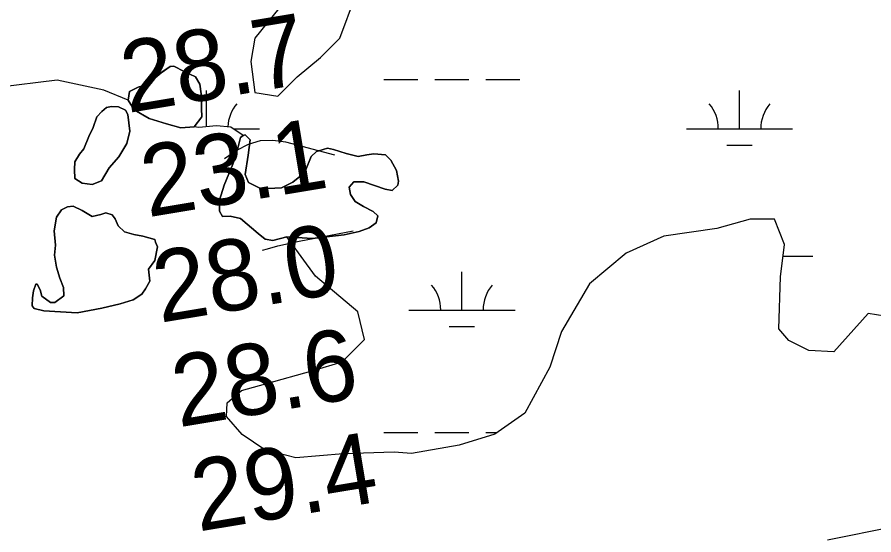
# Model space of a CAD drawing. Extents: x 3297772 to 3335630, y 634068 to 659439.
# Drawn here: x 3328306 to 3329113, y 647977 to 648465 of the extents above; entities that cross this region are included whole.
import ezdxf

# ---------------------------------------------------------------- set-up
doc = ezdxf.new("R2010")
doc.units = 0
for name, color, linetype in [('V-RIVR-EDGE', 7, 'Continuous'), ('V-RIVR-RANG', 7, 'Continuous'), ('V-SITE-VEGE', 7, 'Continuous'), ('V-TOPO-MAJR', 7, 'Continuous'), ('V-TOPO-SHOR', 7, 'Continuous'), ('V-WETL-SWMP', 7, 'Continuous')]:
    doc.layers.add(name, color=color, linetype=linetype)

msp = doc.modelspace()

# ---------------------------------------------------------------- linework, layer by layer
at = {"layer": 'V-RIVR-EDGE'}
msp.add_spline([(3333439.4, 648130.07), (3333432.26, 648128.6), (3333393.46, 648121.33), (3333365.91, 648117.13), (3333332.17, 648114.89), (3333298.43, 648114.2), (3333260.81, 648112.74), (3333230.17, 648112.04), (3333195.26, 648109.02), (3333136.3, 648102.97), (3333088.59, 648097.65), (3333047.08, 648092.71), (3333001.69, 648085.07), (3332967.93, 648078.95), (3332933.41, 648077.1), (3332910.92, 648075.99), (3332895.01, 648074.48), (3332874.46, 648073.36), (3332860.88, 648070.3), (3332849.23, 648064.89), (3332842.24, 648062.97), (3332806.95, 648061.9), (3332785.23, 648058.07), (3332742.94, 648051.2), (3332702.21, 648046.26), (3332606, 648034.47), (3332570.7, 648028.35), (3332514.83, 648018.8), (3332458.57, 648008.85), (3332396.12, 648000.48), (3332317.75, 647987.87), (3332285.55, 647982.52), (3332246.36, 647976.42), (3332207.96, 647971.86), (3332152.88, 647965.79), (3332088.49, 647961.29), (3332048.92, 647954.8), (3332019.05, 647950.22), (3331983.35, 647943.33), (3331945.33, 647935.66), (3331898, 647927.64), (3331843.29, 647918.08), (3331788.98, 647907.74), (3331738.16, 647900.5), (3331714.11, 647898.62), (3331693.93, 647894.02), (3331644.66, 647886.77), (3331609.35, 647880.26), (3331580.26, 647876.07), (3331563.2, 647876.11), (3331548.07, 647876.54), (3331538.38, 647876.17), (3331524.8, 647873.88), (3331503.46, 647868.5), (3331463.88, 647860.46), (3331402.97, 647851.3), (3331393.27, 647846.67), (3331382.01, 647841.27), (3331348.64, 647836.31), (3331302.48, 647830.22), (3331254.77, 647825.68), (3331162.07, 647821.65), (3331119.02, 647820.59), (3331084.5, 647817.19), (3331048.03, 647811.07), (3330992.95, 647804.62), (3330947.56, 647800.07), (3330916.92, 647796.66), (3330882.01, 647795.19), (3330846.71, 647791.4), (3330781.94, 647785.75), (3330745.08, 647780.02), (3330721.81, 647780.08), (3330687.31, 647783.65), (3330659, 647784.89), (3330629.53, 647784.57), (3330565.14, 647780.08), (3330512.78, 647775.17), (3330464.29, 647771.41), (3330411.15, 647764.95), (3330328.91, 647756.62), (3330280.81, 647752.47), (3330223.01, 647743.69), (3330159.77, 647733.77), (3330098.87, 647726.16), (3330018.57, 647717.05), (3329963.87, 647709.43), (3329917.71, 647702.95), (3329903.36, 647702.21), (3329890.56, 647702.25), (3329873.51, 647706.94), (3329862.26, 647707.75), (3329851.79, 647705.83), (3329827.73, 647698.91), (3329814.54, 647697.39), (3329809.49, 647696.63), (3329807.95, 647698.57), (3329806.79, 647701.68), (3329801.75, 647702.08), (3329782.75, 647701.35), (3329745.51, 647698.73), (3329718.75, 647695.69), (3329678.02, 647692.69), (3329648.15, 647688.88), (3329601.98, 647682.02), (3329556.21, 647675.93), (3329520.91, 647674.46), (3329508.12, 647675.27), (3329497.27, 647678.4), (3329465.46, 647674.6), (3329435.21, 647672.74), (3329406.12, 647671.26), (3329386.73, 647673.24), (3329372.01, 647678.71), (3329360.77, 647680.68), (3329347.58, 647681.48), (3329329.36, 647681.14), (3329318.87, 647676.51), (3329309.95, 647675.37), (3329285.52, 647674.66), (3329264.18, 647671.22), (3329230.05, 647668.98), (3329205.62, 647670.98), (3329192.82, 647669.46), (3329173.82, 647668.34), (3329159.86, 647669.54), (3329154.82, 647672.65), (3329142.02, 647669.97), (3329119.52, 647667.31), (3329104.39, 647666.19), (3329092.37, 647665.05), (3329070.26, 647665.11), (3329052.42, 647664.38), (3329042.73, 647664.79), (3329037.31, 647667.13), (3329035.38, 647670.62), (3329031.12, 647672.96), (3329023.36, 647673.37), (3329005.91, 647675.35), (3328975.68, 647679.3), (3328944.66, 647682.09), (3328895.41, 647682.6), (3328867.5, 647686.55), (3328838.8, 647688.56), (3328809.34, 647690.18), (3328773.66, 647691.82), (3328729.06, 647689.61), (3328666.24, 647693.64), (3328624.75, 647694.91), (3328580.16, 647695.79), (3328546.8, 647693.55), (3328506.84, 647687.05), (3328492.87, 647683.21), (3328482.77, 647675.09), (3328471.9, 647673.18), (3328434.28, 647669.78), (3328399.37, 647666.77), (3328372.6, 647660.63), (3328345.83, 647656.43), (3328313.24, 647653.41), (3328276.01, 647651.56), (3328220.15, 647646.27), (3328210.45, 647641.64), (3328198.03, 647638.18), (3328173.59, 647636.69), (3328112.7, 647631.8), (3328044.04, 647626.54), (3328041.33, 647628.48), (3328031.68, 647644.02), (3328021.23, 647654.52), (3328011.16, 647660.36), (3327997.99, 647665.82), (3327984.43, 647668.96), (3327951.08, 647672.14), (3327903.39, 647674.97), (3327857.25, 647678.58), (3327817.69, 647677.9), (3327782.79, 647676.43), (3327750.6, 647676.13), (3327707.94, 647675.46), (3327667.61, 647675.56), (3327640.47, 647680.28), (3327623.8, 647683.03), (3327599.38, 647684.26), (3327563.3, 647682.02), (3327529.17, 647680.16), (3327489.22, 647675.22), (3327442.66, 647667.58), (3327414.73, 647665.71), (3327389.53, 647666.16), (3327373.63, 647665.42), (3327367.43, 647667.38), (3327351.54, 647674.4), (3327334.11, 647680.26), (3327331.79, 647683.75), (3327330.25, 647688.8), (3327320.56, 647691.93), (3327317.47, 647695.81), (3327317.87, 647700.85), (3327315.16, 647702.8), (3327303.15, 647707.09), (3327298.5, 647707.49), (3327292.29, 647704.79), (3327281.81, 647701.72), (3327271.72, 647701.74), (3327235.27, 647702.22), (3327199.21, 647703.47), (3327168.96, 647704.32), (3327108.86, 647708.35), (3327072.81, 647712.7), (3327031.71, 647717.46), (3326986.73, 647719.9), (3326955.32, 647719.2), (3326928.95, 647718.1), (3326908, 647716.21), (3326887.82, 647708.12), (3326876.17, 647702.72), (3326868.8, 647701.96), (3326856.78, 647704.71), (3326842.05, 647704.74), (3326809.47, 647703.27), (3326777.27, 647698.31), (3326760.2, 647695.64), (3326748.94, 647691.4), (3326738.08, 647689.49), (3326737.31, 647691.04), (3326736.93, 647694.92), (3326734.61, 647696.86), (3326712.9, 647700.41), (3326678.39, 647702.05), (3326660.16, 647703.64), (3326628.38, 647711.48), (3326607.84, 647715.41), (3326582.63, 647714.3), (3326557.02, 647710.1), (3326535.69, 647708.99), (3326505.83, 647710.23), (3326475.98, 647711.85), (3326436.81, 647712.73), (3326394.54, 647711.67), (3326361.58, 647711.75), (3326334.82, 647714.14), (3326302.66, 647722.75), (3326245.3, 647737.63), (3326217.01, 647746.62), (3326194.53, 647752.11), (3326171.27, 647755.65), (3326147.62, 647755.32), (3326132.09, 647751.1), (3326110.74, 647743), (3326100.26, 647739.15), (3326091.73, 647738.79), (3326082.82, 647741.52), (3326084.38, 647746.17), (3326084.39, 647749.66), (3326081.3, 647753.16), (3326059.58, 647751.28), (3326025.83, 647748.26), (3325980.44, 647741), (3325936.6, 647735.29)], degree=3, dxfattribs=at)
at = {"layer": 'V-SITE-VEGE'}
msp.add_lwpolyline([(3328559.27, 648481.04), (3328530.13, 648444.6), (3328526.48, 648422.73), (3328530.13, 648393.58), (3328551.98, 648389.93), (3328570.19, 648408.15), (3328592.05, 648426.38), (3328610.26, 648444.6), (3328624.83, 648484.69)], dxfattribs=at)
for points in [[(3328428.72, 648400.97), (3328420.18, 648398.65), (3328412.02, 648394.39), (3328410.84, 648386.23), (3328416.66, 648377.3), (3328430.63, 648369.13), (3328446.93, 648364.06), (3328460.51, 648360.16), (3328472.94, 648361.31), (3328480.33, 648370.62), (3328479.95, 648378.39), (3328479.58, 648392.37), (3328478.42, 648401.3), (3328474.16, 648408.29), (3328463.68, 648413.35), (3328453.98, 648418.41), (3328450.48, 648418.03), (3328441.94, 648412.21)], [(3328369.24, 648340.47), (3328364.97, 648335.42), (3328360.69, 648328.05), (3328360.29, 648321.06), (3328360.67, 648312.52), (3328367.65, 648308.24), (3328376.97, 648306.68), (3328385.9, 648310.16), (3328392.91, 648322.58), (3328402.24, 648333.05), (3328409.63, 648345.47), (3328412.36, 648357.11), (3328410.44, 648372.65), (3328408.5, 648376.92), (3328401.91, 648380.03), (3328395.3, 648380.43), (3328390.64, 648379.27), (3328385.98, 648375.78), (3328381.31, 648370.74), (3328377.81, 648360.65), (3328373.92, 648352.11)], [(3328583.18, 648333.23), (3328577.73, 648320.03), (3328574.23, 648315.77), (3328566.07, 648309.17), (3328555.19, 648303.75), (3328536.16, 648302.61), (3328524.13, 648308.83), (3328521.04, 648316.22), (3328523.77, 648334.46), (3328525.73, 648348.83), (3328521.08, 648353.49), (3328519.13, 648353.1), (3328516.8, 648351.17), (3328514.07, 648341.07), (3328509.4, 648325.94), (3328501.22, 648306.14), (3328496.93, 648292.17), (3328496.92, 648281.69), (3328499.63, 648276.64), (3328507.01, 648277.02), (3328516.71, 648274.68), (3328533.4, 648260.68), (3328539.99, 648255.23), (3328546.98, 648254.06), (3328560.18, 648257.54), (3328584.25, 648255.96), (3328614.16, 648259.42), (3328628.53, 648262.51), (3328637.85, 648265.99), (3328644.46, 648270.64), (3328646.02, 648277.24), (3328641.75, 648281.52), (3328632.44, 648286.19), (3328624.68, 648290.86), (3328620.41, 648297.46), (3328618.87, 648304.45), (3328623.53, 648309.5), (3328632.85, 648309.48), (3328642.94, 648305.98), (3328653.04, 648302.47), (3328659.63, 648301.3), (3328664.69, 648306.34), (3328665.47, 648309.84), (3328663.54, 648319.93), (3328658.11, 648329.65), (3328653.07, 648334.7), (3328642.2, 648335.88), (3328635.6, 648334.72), (3328627.44, 648333.18), (3328616.19, 648335.91), (3328604.16, 648339.81), (3328598.72, 648340.98), (3328590.56, 648338.66), (3328588.23, 648337.88)], [(3328341.2, 648263.23), (3328342.35, 648249.64), (3328341.56, 648240.32), (3328343.49, 648229.06), (3328346.58, 648218.57), (3328350.07, 648209.64), (3328350.45, 648201.87), (3328341.89, 648195.67), (3328337.62, 648195.67), (3328329.48, 648201.51), (3328327.93, 648207.72), (3328325.22, 648212.77), (3328324.05, 648212.77), (3328321.71, 648206.56), (3328320.93, 648199.96), (3328320.54, 648192.59), (3328322.47, 648189.86), (3328331.4, 648187.91), (3328362.85, 648185.94), (3328386.15, 648190.18), (3328403.24, 648194.43), (3328415.67, 648198.3), (3328423.83, 648203.34), (3328427.33, 648208.38), (3328431.22, 648215.76), (3328430.07, 648227.02), (3328435.91, 648235.16), (3328438.64, 648247.97), (3328436.7, 648252.63), (3328435.93, 648254.97), (3328430.5, 648256.53), (3328424.67, 648258.09), (3328416.13, 648259.65), (3328407.59, 648262.38), (3328401.39, 648267.82), (3328398.68, 648274.42), (3328395.96, 648278.31), (3328389.75, 648280.26), (3328385.09, 648278.71), (3328376.93, 648276.78), (3328367.62, 648282.23), (3328359.08, 648286.51), (3328353.65, 648285.74), (3328348.21, 648283.02), (3328343.54, 648276.04)]]:
    msp.add_lwpolyline(points, close=True, dxfattribs=at)
at = {"layer": 'V-TOPO-MAJR'}
for points in [[(3328605.59, 648334.44), (3328559.28, 648346.82), (3328547.08, 648348.38), (3328535.22, 648347.91), (3328523.89, 648344.4), (3328512.91, 648338.85), (3328501.46, 648330.99)], [(3328537.49, 648244.85), (3328542.15, 648246.22), (3328551.95, 648248.88), (3328561.84, 648251.21), (3328571.79, 648253.33), (3328622.77, 648263.28)]]:
    msp.add_lwpolyline(points, dxfattribs=at)
at = {"layer": 'V-TOPO-SHOR'}
for points in [[(3328428.72, 648400.97), (3328441.94, 648412.21), (3328450.48, 648418.03), (3328453.98, 648418.41), (3328463.68, 648413.35), (3328474.16, 648408.29), (3328478.42, 648401.3), (3328479.58, 648392.37), (3328479.95, 648378.39), (3328480.33, 648370.62), (3328472.94, 648361.31), (3328460.51, 648360.16), (3328446.93, 648364.06), (3328430.63, 648369.13), (3328416.66, 648377.3), (3328410.84, 648386.23), (3328412.02, 648394.39), (3328420.18, 648398.65), (3328428.72, 648400.97)], [(3328369.24, 648340.47), (3328373.92, 648352.11), (3328377.81, 648360.65), (3328381.31, 648370.74), (3328385.98, 648375.78), (3328390.64, 648379.27), (3328395.3, 648380.43), (3328401.91, 648380.03), (3328408.5, 648376.92), (3328410.44, 648372.65), (3328412.36, 648357.11), (3328409.63, 648345.47), (3328402.24, 648333.05), (3328392.91, 648322.58), (3328385.9, 648310.16), (3328376.97, 648306.68), (3328367.65, 648308.24), (3328360.67, 648312.52), (3328360.29, 648321.06), (3328360.69, 648328.05), (3328364.97, 648335.42), (3328369.24, 648340.47)], [(3328583.18, 648333.23), (3328588.23, 648337.88), (3328590.56, 648338.66), (3328598.72, 648340.98), (3328604.16, 648339.81), (3328616.19, 648335.91), (3328627.44, 648333.18), (3328635.6, 648334.72), (3328642.2, 648335.88), (3328653.07, 648334.7), (3328658.11, 648329.65), (3328663.54, 648319.93), (3328665.47, 648309.84), (3328664.69, 648306.34), (3328659.63, 648301.3), (3328653.04, 648302.47), (3328642.94, 648305.98), (3328632.85, 648309.48), (3328623.53, 648309.5), (3328618.87, 648304.45), (3328620.41, 648297.46), (3328624.68, 648290.86), (3328632.44, 648286.19), (3328641.75, 648281.52), (3328646.02, 648277.24), (3328644.46, 648270.64), (3328637.85, 648265.99), (3328628.53, 648262.51), (3328614.16, 648259.42), (3328584.25, 648255.96), (3328560.18, 648257.54), (3328546.98, 648254.06), (3328539.99, 648255.23), (3328533.4, 648260.68), (3328516.71, 648274.68), (3328507.01, 648277.02), (3328499.63, 648276.64), (3328496.92, 648281.69), (3328496.93, 648292.17), (3328501.22, 648306.14), (3328509.4, 648325.94), (3328514.07, 648341.07), (3328516.8, 648351.17), (3328519.13, 648353.1), (3328521.08, 648353.49), (3328525.73, 648348.83), (3328523.77, 648334.46), (3328521.04, 648316.22), (3328524.13, 648308.83), (3328536.16, 648302.61), (3328555.19, 648303.75), (3328566.07, 648309.17), (3328574.23, 648315.77), (3328577.73, 648320.03), (3328583.18, 648333.23)], [(3328341.2, 648263.23), (3328343.54, 648276.04), (3328348.21, 648283.02), (3328353.65, 648285.74), (3328359.08, 648286.51), (3328367.62, 648282.23), (3328376.93, 648276.78), (3328385.09, 648278.71), (3328389.75, 648280.26), (3328395.96, 648278.31), (3328398.68, 648274.42), (3328401.39, 648267.82), (3328407.59, 648262.38), (3328416.13, 648259.65), (3328424.67, 648258.09), (3328430.5, 648256.53), (3328435.93, 648254.97), (3328436.7, 648252.63), (3328438.64, 648247.97), (3328435.91, 648235.16), (3328430.07, 648227.02), (3328431.22, 648215.76), (3328427.33, 648208.38), (3328423.83, 648203.34), (3328415.67, 648198.3), (3328403.24, 648194.43), (3328386.15, 648190.18), (3328362.85, 648185.94), (3328331.4, 648187.91), (3328322.47, 648189.86), (3328320.54, 648192.59), (3328320.93, 648199.96), (3328321.71, 648206.56), (3328324.05, 648212.77), (3328325.22, 648212.77), (3328327.93, 648207.72), (3328329.48, 648201.51), (3328337.62, 648195.67), (3328341.89, 648195.67), (3328350.45, 648201.87), (3328350.07, 648209.64), (3328346.58, 648218.57), (3328343.49, 648229.06), (3328341.56, 648240.32), (3328342.35, 648249.64), (3328341.2, 648263.23)]]:
    msp.add_lwpolyline(points, dxfattribs=at)
at = {"layer": 'V-WETL-SWMP'}
for p, q in [((3328450.49, 648418.03), (3328441.94, 648412.22)), ((3328453.98, 648418.41), (3328450.49, 648418.03)), ((3328463.68, 648413.36), (3328453.98, 648418.41)), ((3328441.94, 648412.22), (3328428.72, 648400.97)), ((3328474.16, 648408.3), (3328463.68, 648413.36)), ((3328478.42, 648401.3), (3328474.16, 648408.3)), ((3328343.91, 648405.14), (3328248.69, 648393.22)), ((3328387.84, 648395.68), (3328343.91, 648405.14)), ((3328428.72, 648400.97), (3328420.18, 648398.65)), ((3328479.58, 648392.37), (3328478.42, 648401.3)), ((3328651.76, 648405.77), (3328683.76, 648405.77)), ((3328699.76, 648405.77), (3328731.76, 648405.77)), ((3328747.76, 648405.77), (3328779.76, 648405.77)), ((3328410.84, 648386.24), (3328387.84, 648395.68)), ((3328412.02, 648394.39), (3328410.84, 648386.24)), ((3328420.18, 648398.65), (3328412.02, 648394.39)), ((3328479.95, 648378.39), (3328479.58, 648392.37)), ((3328484.69, 648361.16), (3328484.69, 648395.34)), ((3328986.6, 648359.34), (3328986.6, 648395.34)), ((3328480.33, 648370.63), (3328479.95, 648378.39)), ((3328472.94, 648361.32), (3328480.33, 648370.63)), ((3328477.3, 648360.48), (3328472.94, 648361.32)), ((3328494.04, 648362.03), (3328477.3, 648360.48)), ((3328507.64, 648360.97), (3328494.04, 648362.03)), ((3328519.14, 648353.11), (3328507.64, 648360.97)), ((3328510.02, 648359.34), (3328534.69, 648359.34)), ((3328936.6, 648359.34), (3329036.6, 648359.34)), ((3328521.08, 648353.49), (3328519.14, 648353.11)), ((3328525.73, 648348.83), (3328521.08, 648353.49)), ((3328523.77, 648334.46), (3328525.73, 648348.83)), ((3328974.6, 648343.91), (3328998.6, 648343.91)), ((3328588.23, 648337.88), (3328583.18, 648333.23)), ((3328590.56, 648338.66), (3328588.23, 648337.88)), ((3328598.72, 648340.98), (3328590.56, 648338.66)), ((3328604.15, 648339.81), (3328598.72, 648340.98)), ((3328616.19, 648335.91), (3328604.15, 648339.81)), ((3328627.44, 648333.18), (3328616.19, 648335.91)), ((3328642.2, 648335.88), (3328635.6, 648334.72)), ((3328653.07, 648334.7), (3328642.2, 648335.88)), ((3328521.03, 648316.22), (3328523.77, 648334.46)), ((3328583.18, 648333.23), (3328577.73, 648320.03)), ((3328635.6, 648334.72), (3328627.44, 648333.18)), ((3328658.11, 648329.65), (3328653.07, 648334.7)), ((3328663.54, 648319.93), (3328658.11, 648329.65)), ((3328577.73, 648320.03), (3328574.23, 648315.77)), ((3328665.47, 648309.84), (3328663.54, 648319.93)), ((3328524.13, 648308.84), (3328521.03, 648316.22)), ((3328574.23, 648315.77), (3328566.07, 648309.18)), ((3328536.16, 648302.61), (3328524.13, 648308.84)), ((3328555.19, 648303.75), (3328536.16, 648302.61)), ((3328566.07, 648309.18), (3328555.19, 648303.75)), ((3328618.87, 648304.46), (3328623.53, 648309.5)), ((3328620.41, 648297.46), (3328618.87, 648304.46)), ((3328623.53, 648309.5), (3328632.85, 648309.49)), ((3328632.85, 648309.49), (3328642.94, 648305.98)), ((3328642.94, 648305.98), (3328653.03, 648302.47)), ((3328659.63, 648301.3), (3328664.69, 648306.34)), ((3328664.69, 648306.34), (3328665.47, 648309.84)), ((3328624.68, 648290.86), (3328620.41, 648297.46)), ((3328653.03, 648302.47), (3328659.63, 648301.3)), ((3328632.44, 648286.19), (3328624.68, 648290.86)), ((3328641.75, 648281.52), (3328632.44, 648286.19)), ((3328646.02, 648277.24), (3328641.75, 648281.52)), ((3328637.85, 648265.99), (3328644.46, 648270.64)), ((3328644.46, 648270.64), (3328646.02, 648277.24)), ((3328996.45, 648274.29), (3328965.06, 648265.44)), ((3329019.47, 648274.27), (3328996.45, 648274.29)), ((3329028.85, 648250.19), (3329019.47, 648274.27)), ((3328614.16, 648259.42), (3328628.53, 648262.51)), ((3328628.53, 648262.51), (3328637.85, 648265.99)), ((3328965.06, 648265.44), (3328915.36, 648258.17)), ((3328587.34, 648220.37), (3328560.18, 648257.54)), ((3328560.18, 648257.54), (3328584.25, 648255.96)), ((3328584.25, 648255.96), (3328614.16, 648259.42)), ((3328915.36, 648258.17), (3328879.77, 648242)), ((3329025.16, 648219.86), (3329028.85, 648250.19)), ((3328879.77, 648242), (3328845.21, 648213.27)), ((3329027.52, 648239.27), (3329055.76, 648239.27)), ((3328725.17, 648188.53), (3328725.17, 648224.53)), ((3328627.05, 648186.85), (3328587.34, 648220.37)), ((3329023.53, 648170.69), (3329025.16, 648219.86)), ((3328845.21, 648213.27), (3328819, 648168.31)), ((3328633.3, 648160.68), (3328627.05, 648186.85)), ((3328675.17, 648188.53), (3328775.17, 648188.53)), ((3329107.76, 648185.24), (3329075.29, 648149.19)), ((3329131.3, 648181.55), (3329107.76, 648185.24)), ((3328713.17, 648173.09), (3328737.17, 648173.09)), ((3328819, 648168.31), (3328807.98, 648134.85)), ((3329032.93, 648159.7), (3329023.53, 648170.69)), ((3328612.35, 648139.78), (3328633.3, 648160.68)), ((3329051.75, 648150.26), (3329032.93, 648159.7)), ((3329075.29, 648149.19), (3329051.75, 648150.26)), ((3328585.14, 648131.45), (3328612.35, 648139.78)), ((3328807.98, 648134.85), (3328784.39, 648091.46)), ((3328540.14, 648118.94), (3328585.14, 648131.45)), ((3328517.64, 648112.7), (3328540.14, 648118.94)), ((3328504.03, 648101.2), (3328517.64, 648112.7)), ((3328503.49, 648088.13), (3328504.03, 648101.2)), ((3328518.12, 648071.37), (3328503.49, 648088.13)), ((3328784.39, 648091.46), (3328756.12, 648071.62)), ((3328539.55, 648056.7), (3328518.12, 648071.37)), ((3328651.76, 648073.09), (3328683.76, 648073.09)), ((3328699.76, 648073.09), (3328731.76, 648073.09)), ((3328756.12, 648071.62), (3328722.63, 648061.19)), ((3328747.76, 648073.09), (3328758.23, 648073.09)), ((3328722.63, 648061.19), (3328677.64, 648053.4)), ((3328568.83, 648049.34), (3328539.55, 648056.7)), ((3328613.3, 648052.95), (3328568.83, 648049.34)), ((3328661.42, 648054.46), (3328613.3, 648052.95)), ((3328677.64, 648053.4), (3328661.42, 648054.46)), ((3329069.33, 647971.87), (3329188.1, 647995.79))]:
    msp.add_line(p, q, dxfattribs=at)
for centre, start, end in [((3328539.94, 648359.81), 139.22818, 177.75672), ((3328931.36, 648359.81), 359.22818, 40.77184), ((3329041.84, 648359.81), 139.22818, 180.77184), ((3328669.92, 648189), 359.22818, 40.77184), ((3328780.41, 648189), 139.22818, 180.77184)]:
    msp.add_arc(centre, 35.25, start, end, dxfattribs=at)

# ---------------------------------------------------------------- texts
at = {"layer": 'V-RIVR-RANG'}
for s, p in [('28.7', (3328410.33, 648374.08)), ('23.1', (3328429.3, 648275.86)), ('28.0', (3328440.73, 648176.39)), ('28.6', (3328458.4, 648077.96)), ('29.4', (3328476.85, 647979.65))]:
    msp.add_text(s, height=67, rotation=9.42833, dxfattribs=at).set_placement(p)

doc.saveas('drawing.dxf')
